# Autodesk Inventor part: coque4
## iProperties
Created: 2008-12
Part Number: coque4
Document SubType Name: Modeling
Designer: LCM
Author: LCM
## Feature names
1. Lissage3
2. Lissage4
3. Lissage5
4. Balayage1
5. Extrusion3
6. Extrusion4
7. Extrusion5
8. Extrusion6
9. Extrusion7
10. Miroir1 [Mirror]
11. Extrusion11
